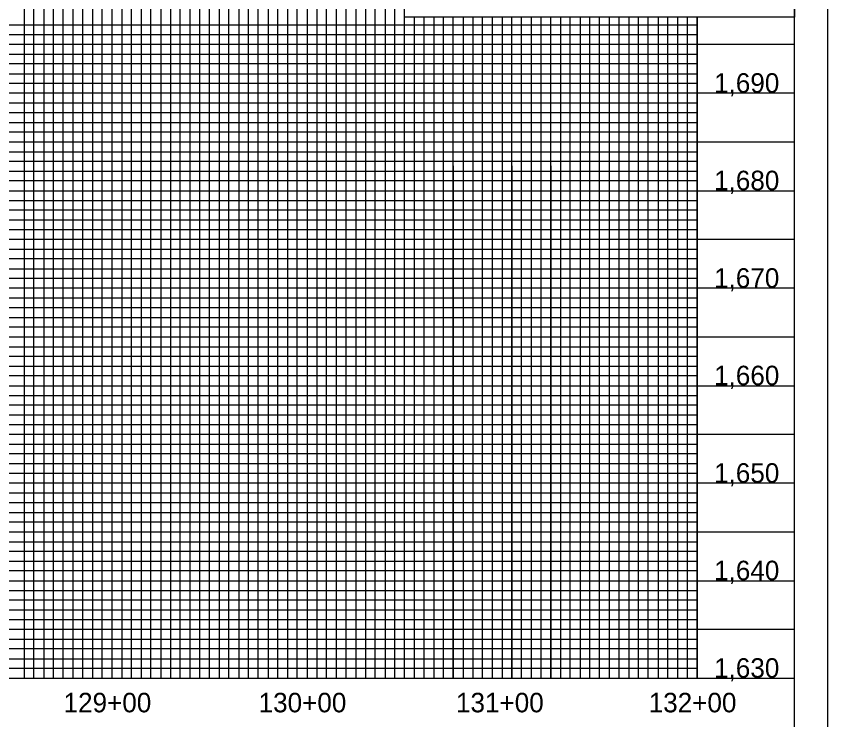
# Model space of a CAD drawing. Extents: x 505602 to 507286, y 483109 to 484209.
# Drawn here: x 506870 to 507286.1, y 483662.4 to 484023.2 of the extents above; entities that cross this region are included whole.
import ezdxf

# ---------------------------------------------------------------- set-up
doc = ezdxf.new("R2010")
doc.units = 0
for name, color, linetype in [('Exist Vertical Profile Vertical Axis Label', 7, 'Continuous'), ('Sheet Layout Profile Border Port 1', 7, 'Continuous'), ('Sheet Plot Border Outside CELL', 7, 'Continuous'), ('Sheet Profile CELL', 7, 'Continuous'), ('Sheet Profile Grid Major CELL', 7, 'Continuous'), ('Sheet Profile Grid Middle CELL', 7, 'Continuous'), ('Sheet Profile Grid Minor CELL', 7, 'Continuous'), ('Sheet Sticker Exception Certification CELL', 7, 'Continuous')]:
    doc.layers.add(name, color=color, linetype=linetype)

msp = doc.modelspace()

# ---------------------------------------------------------------- linework, layer by layer
at = {"layer": 'Sheet Layout Profile Border Port 1'}
msp.add_lwpolyline([(505819.08, 484183.71), (505819.08, 483683.71), (507219.08, 483683.71), (507219.08, 484022.66), (507069.03, 484022.66), (507069.03, 484183.71)], close=True, dxfattribs=at)
at = {"layer": 'Sheet Plot Border Outside CELL'}
msp.add_lwpolyline([(505602.08, 483108.71), (507286.08, 483108.71), (507286.08, 484208.71), (505602.08, 484208.71)], close=True, dxfattribs=at)
at = {"layer": 'Sheet Profile CELL'}
msp.add_line((505769.08, 483683.71), (507269.08, 483683.71), dxfattribs=at)
msp.add_lwpolyline([(507269.08, 484183.71), (505769.08, 484183.71), (505769.08, 483133.71), (507269.08, 483133.71)], close=True, dxfattribs=at)
at = {"layer": 'Sheet Profile Grid Major CELL'}
for points in [[(506869.08, 484183.71), (506919.08, 484183.71), (506919.08, 483683.71), (506969.08, 483683.71), (506969.08, 484183.71), (507019.08, 484183.71), (507019.08, 483683.71), (507069.08, 483683.71), (507069.08, 484183.71), (507095.38, 484183.71)], [(507219.08, 484022.66), (507219.08, 483683.71), (507269.08, 483683.71), (507269.08, 484033.71)], [(507119.08, 484022.66), (507119.08, 483683.71), (507169.08, 483683.71), (507169.08, 483683.71), (507169.08, 484022.66)], [(507269.08, 483983.71), (505769.08, 483983.71), (505769.08, 483933.71), (507269.08, 483933.71)], [(507269.08, 483883.71), (505769.08, 483883.71), (505769.08, 483833.71), (507269.08, 483833.71)], [(507269.08, 483783.71), (505769.08, 483783.71), (505769.08, 483783.71), (505769.08, 483733.71), (507269.08, 483733.71)]]:
    msp.add_lwpolyline(points, dxfattribs=at)
at = {"layer": 'Sheet Profile Grid Middle CELL'}
for points in [[(506844.08, 483683.71), (506894.08, 483683.71), (506894.08, 484183.71), (506944.08, 484183.71), (506944.08, 483683.71), (506994.08, 483683.71), (506994.08, 484183.71), (507044.08, 484183.71), (507044.08, 483683.71), (507094.08, 483683.71), (507094.08, 484022.66)], [(507094.08, 483946.51), (507094.08, 483683.71), (507144.08, 483683.71), (507144.08, 484022.66)], [(507144.08, 483946.51), (507144.08, 483683.71), (507194.08, 483683.71), (507194.08, 484022.66)], [(507269.08, 484008.71), (505769.08, 484008.71), (505769.08, 483958.71), (507094.08, 483958.71)], [(507094.08, 483958.71), (507269.08, 483958.71)], [(507269.08, 483908.71), (505769.08, 483908.71), (505769.08, 483858.71), (507269.08, 483858.71)], [(507269.08, 483808.71), (505769.08, 483808.71), (505769.08, 483758.71), (507269.08, 483758.71)], [(507269.08, 483708.71), (505769.08, 483708.71)]]:
    msp.add_lwpolyline(points, dxfattribs=at)
at = {"layer": 'Sheet Profile Grid Minor CELL'}
for p, q in [((505819.08, 484018.71), (507219.08, 484018.71)), ((507219.08, 483998.71), (505819.08, 483998.71)), ((505819.08, 483993.71), (507219.08, 483993.71)), ((507219.08, 483973.71), (505819.08, 483973.71)), ((505819.08, 483968.71), (507219.08, 483968.71)), ((507219.08, 483948.71), (505819.08, 483948.71)), ((505819.08, 483943.71), (507219.08, 483943.71)), ((507219.08, 483938.71), (505819.08, 483938.71)), ((505819.08, 483928.71), (507219.08, 483928.71)), ((507219.08, 483923.71), (505819.08, 483923.71)), ((505819.08, 483918.71), (507219.08, 483918.71)), ((507219.08, 483913.71), (505819.08, 483913.71)), ((505819.08, 483903.71), (507219.08, 483903.71)), ((507219.08, 483898.71), (505819.08, 483898.71)), ((505819.08, 483893.71), (507219.08, 483893.71)), ((507219.08, 483888.71), (505819.08, 483888.71)), ((505819.08, 483878.71), (507219.08, 483878.71)), ((507219.08, 483873.71), (505819.08, 483873.71)), ((505819.08, 483868.71), (507219.08, 483868.71)), ((507219.08, 483863.71), (505819.08, 483863.71)), ((505819.08, 483853.71), (507219.08, 483853.71)), ((507219.08, 483848.71), (505819.08, 483848.71)), ((505819.08, 483843.71), (507219.08, 483843.71)), ((507219.08, 483838.71), (505819.08, 483838.71)), ((505819.08, 483828.71), (507219.08, 483828.71)), ((507219.08, 483823.71), (505819.08, 483823.71)), ((505819.08, 483818.71), (507219.08, 483818.71)), ((507219.08, 483813.71), (505819.08, 483813.71)), ((505819.08, 483803.71), (507219.08, 483803.71)), ((507219.08, 483798.71), (505819.08, 483798.71)), ((507219.08, 483793.71), (505819.08, 483793.71)), ((507219.08, 483788.71), (505819.08, 483788.71)), ((505819.08, 483778.71), (507219.08, 483778.71)), ((507219.08, 483773.71), (505819.08, 483773.71)), ((505819.08, 483768.71), (507219.08, 483768.71)), ((507219.08, 483763.71), (505819.08, 483763.71)), ((505819.08, 483753.71), (507219.08, 483753.71)), ((507219.08, 483748.71), (505819.08, 483748.71)), ((505819.08, 483743.71), (507219.08, 483743.71)), ((507219.08, 483738.71), (505819.08, 483738.71)), ((505819.08, 483728.71), (507219.08, 483728.71)), ((507219.08, 483723.71), (505819.08, 483723.71)), ((505819.08, 483718.71), (507219.08, 483718.71)), ((507219.08, 483713.71), (505819.08, 483713.71)), ((505819.08, 483703.71), (507219.08, 483703.71)), ((507219.08, 483698.71), (505819.08, 483698.71)), ((505819.08, 483693.71), (507219.08, 483693.71))]:
    msp.add_line(p, q, dxfattribs=at)
for points in [[(506874.08, 484183.71), (506874.08, 483683.71), (506879.08, 483683.71), (506879.08, 484183.71)], [(506884.08, 484183.71), (506884.08, 483683.71), (506889.08, 483683.71), (506889.08, 484183.71)], [(506899.08, 484183.71), (506899.08, 483683.71), (506904.08, 483683.71), (506904.08, 484183.71)], [(506909.08, 484183.71), (506909.08, 483683.71), (506914.08, 483683.71), (506914.08, 484183.71)], [(506924.08, 484183.71), (506924.08, 483683.71), (506929.08, 483683.71), (506929.08, 484183.71)], [(506934.08, 484183.71), (506934.08, 483683.71), (506939.08, 483683.71), (506939.08, 484183.71)], [(506949.08, 484183.71), (506949.08, 483683.71), (506954.08, 483683.71), (506954.08, 484183.71)], [(506959.08, 484183.71), (506959.08, 483683.71)], [(506959.08, 483683.71), (506964.08, 483683.71), (506964.08, 484183.71)], [(506974.08, 484183.71), (506974.08, 483683.71), (506979.08, 483683.71), (506979.08, 484183.71)], [(506984.08, 484183.71), (506984.08, 483683.71), (506989.08, 483683.71), (506989.08, 484183.71)], [(506999.08, 484183.71), (506999.08, 483683.71), (507004.08, 483683.71), (507004.08, 484183.71)], [(507009.08, 484183.71), (507009.08, 483683.71), (507014.08, 483683.71), (507014.08, 484183.71)], [(507024.08, 484183.71), (507024.08, 483683.71), (507029.08, 483683.71), (507029.08, 484183.71)], [(507034.08, 484183.71), (507034.08, 483683.71), (507039.08, 483683.71), (507039.08, 484183.71)], [(507049.08, 484183.71), (507049.08, 483683.71), (507054.08, 483683.71), (507054.08, 484183.71)], [(507059.08, 484183.71), (507059.08, 483683.71), (507064.08, 483683.71), (507064.08, 484183.71)], [(507074.08, 484022.66), (507074.08, 483683.71), (507079.08, 483683.71), (507079.08, 484022.66)], [(507084.08, 484022.66), (507084.08, 483683.71), (507089.08, 483683.71), (507089.08, 484022.66)], [(507099.08, 484022.66), (507099.08, 483683.71), (507099.08, 483683.71), (507104.08, 483683.71), (507109.08, 483683.71), (507109.08, 484022.66)], [(507104.08, 484022.66), (507104.08, 483683.71)], [(507114.07, 484022.66), (507113.98, 483683.76), (507118.98, 483683.76), (507124.08, 483683.71), (507124.08, 484022.66)], [(507124.08, 483946.51), (507124.08, 483683.71), (507129.08, 483683.71), (507129.08, 484022.66)], [(507134.08, 484022.66), (507134.08, 483683.71), (507139.08, 483683.71), (507139.08, 484022.66)], [(507149.08, 484022.66), (507149.08, 483683.71), (507154.08, 483683.71), (507154.08, 484022.66)], [(507159.08, 484022.66), (507159.08, 483683.71), (507164.08, 483683.71), (507164.08, 484022.66)], [(507174.08, 484022.66), (507174.08, 483683.71), (507179.08, 483683.71), (507179.08, 484022.66)], [(507184.08, 484022.66), (507184.08, 483683.71), (507189.08, 483683.71), (507189.08, 484022.66)], [(507199.08, 484022.66), (507199.08, 483683.71), (507204.08, 483683.71), (507204.08, 484022.66)], [(507209.08, 484022.66), (507209.08, 483683.71), (507214.08, 483683.71), (507214.08, 484022.66)], [(507219.08, 484013.71), (505819.08, 484013.71), (505819.08, 484003.71), (507219.08, 484003.71)], [(507219.08, 483988.71), (505819.08, 483988.71), (505819.08, 483978.71), (507219.08, 483978.71)], [(507219.08, 483963.71), (505819.08, 483963.71), (505819.08, 483953.71), (507219.08, 483953.71)], [(507219.08, 483688.71), (505819.08, 483688.71)]]:
    msp.add_lwpolyline(points, dxfattribs=at)
at = {"layer": 'Sheet Sticker Exception Certification CELL'}
for p, q in [((507069.03, 484022.66), (507069.03, 484046.16)), ((507069.03, 484022.66), (507069.03, 484046.16)), ((507269.07, 484046.15), (507269.07, 484022.65)), ((507269.07, 484046.15), (507269.07, 484022.65)), ((507269.07, 484022.66), (507069.03, 484022.66)), ((507269.07, 484022.66), (507069.03, 484022.66))]:
    msp.add_line(p, q, dxfattribs=at)

# ---------------------------------------------------------------- texts
at = {"layer": 'Exist Vertical Profile Vertical Axis Label'}
for s, p in [('1,690', (507227.78, 483983.96)), ('1,680', (507227.78, 483933.96)), ('1,670', (507227.78, 483883.96)), ('1,660', (507227.78, 483833.96)), ('1,650', (507227.78, 483783.96)), ('1,640', (507227.78, 483733.96)), ('1,630', (507227.78, 483683.96)), ('129+00', (506894.26, 483666.21)), ('130+00', (506994.26, 483666.21)), ('131+00', (507095.45, 483666.21)), ('132+00', (507194.26, 483666.21))]:
    msp.add_text(s, height=10, dxfattribs=at).set_placement(p)

doc.saveas('drawing.dxf')
